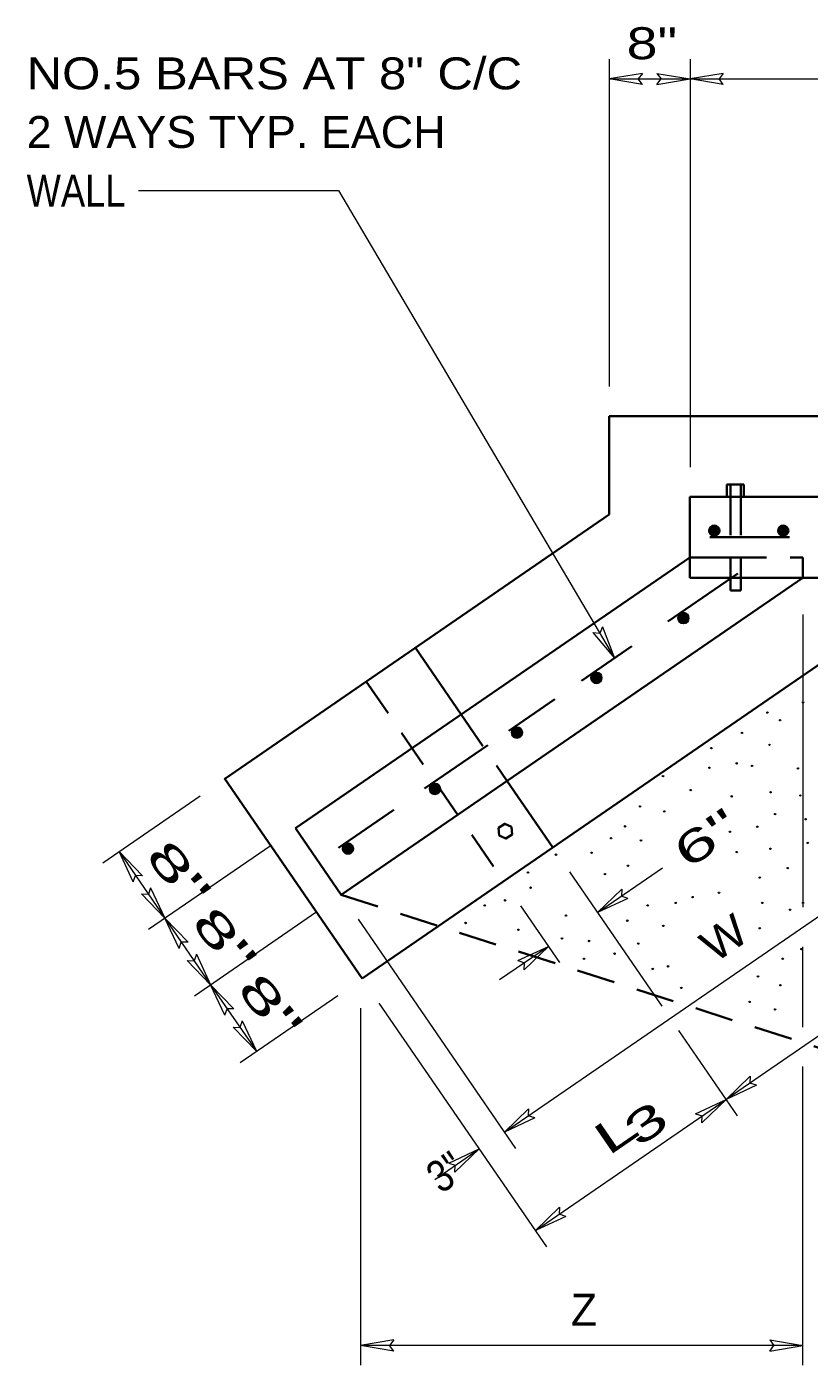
# Model space of a CAD drawing. Extents: x 178962.5 to 178977.5, y 178951.2 to 178972.9.
# Drawn here: x 178970.1 to 178973.41, y 178967.18 to 178972.83 of the extents above; entities that cross this region are included whole.
import ezdxf
from ezdxf.enums import TextEntityAlignment as Align

# ---------------------------------------------------------------- set-up
doc = ezdxf.new("R2010")
doc.units = 0
doc.header["$LTSCALE"] = 0.054
doc.linetypes.add('LONG_DASHED', pattern=[7.5, 6, -1.5])
doc.linetypes.add('MEDIUM_DASHED', pattern=[4.5, 3, -1.5])
for name, color, linetype, lineweight in [('1', 7, 'Continuous', 35), ('10', 7, 'Continuous', 13), ('12', 7, 'Continuous', 53), ('6', 7, 'Continuous', 13)]:
    doc.layers.add(name, color=color, linetype=linetype, lineweight=lineweight)

msp = doc.modelspace()

# ---------------------------------------------------------------- linework, layer by layer
at = {"layer": '1'}
for p, q in [((178972.56175, 178970.77058), (178972.56175, 178971.18683)), ((178972.56175, 178971.18683), (178973.67117, 178971.18683)), ((178973.13008, 178970.89825), (178973.05833, 178970.89825)), ((178973.05833, 178970.89825), (178973.05833, 178970.8455)), ((178973.07325, 178970.897), (178973.07325, 178970.8455)), ((178973.11708, 178970.89742), (178973.11708, 178970.8455)), ((178973.13008, 178970.89825), (178973.13008, 178970.8455)), ((178972.9015, 178970.8455), (178972.9015, 178970.50417)), ((178975.7175, 178970.8455), (178972.9015, 178970.8455)), ((178973.01008, 178970.72417), (178972.98367, 178970.7005)), ((178973.00217, 178970.72442), (178972.98417, 178970.70842)), ((178973.01583, 178970.72192), (178972.98517, 178970.6945)), ((178973.02033, 178970.71867), (178972.98792, 178970.68967)), ((178973.02383, 178970.71442), (178972.99167, 178970.68575)), ((178973.02617, 178970.70925), (178972.99658, 178970.68283)), ((178973.02717, 178970.70283), (178973.00283, 178970.68117)), ((178973.02525, 178970.69375), (178973.01217, 178970.682)), ((178973.301, 178970.72417), (178973.2745, 178970.7005)), ((178973.29308, 178970.72442), (178973.27517, 178970.70842)), ((178973.30675, 178970.72192), (178973.276, 178970.69458)), ((178973.31117, 178970.71875), (178973.27883, 178970.68975)), ((178973.31475, 178970.71442), (178973.28258, 178970.68575)), ((178973.31717, 178970.70933), (178973.2875, 178970.68275)), ((178973.31808, 178970.70283), (178973.29383, 178970.68108)), ((178973.31617, 178970.69375), (178973.30308, 178970.68208)), ((178972.98683, 178970.67483), (178973.32233, 178970.67483)), ((178972.9015, 178970.58992), (178971.23658, 178969.4455)), ((178973.10483, 178970.52225), (178972.80867, 178970.31892)), ((178973.37925, 178970.50417), (178971.42992, 178969.16417)), ((178975.7175, 178970.50417), (178972.9015, 178970.50417)), ((178972.87992, 178970.35492), (178972.85342, 178970.33125)), ((178972.872, 178970.35517), (178972.85408, 178970.33917)), ((178972.88567, 178970.35275), (178972.85492, 178970.32533)), ((178972.89008, 178970.3495), (178972.85775, 178970.3205)), ((178972.89367, 178970.34525), (178972.86158, 178970.31658)), ((178972.89608, 178970.34008), (178972.86642, 178970.31358)), ((178972.89708, 178970.33358), (178972.87275, 178970.31192)), ((178972.89508, 178970.32458), (178972.882, 178970.31283)), ((178971.74325, 178970.208), (178971.93658, 178969.92667)), ((178972.44492, 178970.069), (178972.65658, 178970.21442)), ((178973.48525, 178970.16283), (178971.51783, 178968.81042)), ((178972.51208, 178970.10208), (178972.48567, 178970.07842)), ((178972.50425, 178970.10233), (178972.48625, 178970.08633)), ((178972.51792, 178970.09983), (178972.48717, 178970.07242)), ((178972.52233, 178970.09658), (178972.49, 178970.06758)), ((178972.52592, 178970.09233), (178972.49367, 178970.06375)), ((178972.52825, 178970.08717), (178972.49867, 178970.06075)), ((178972.52925, 178970.08075), (178972.50492, 178970.059)), ((178972.52733, 178970.07175), (178972.51417, 178970.05992)), ((178972.13783, 178969.85792), (178972.33217, 178969.9915)), ((178972.17658, 178969.87142), (178972.15017, 178969.84775)), ((178972.16875, 178969.87175), (178972.15075, 178969.85575)), ((178972.18233, 178969.86933), (178972.15167, 178969.84183)), ((178972.18692, 178969.86608), (178972.15442, 178969.83708)), ((178972.19033, 178969.86175), (178972.15825, 178969.83308)), ((178972.19275, 178969.85667), (178972.16317, 178969.83008)), ((178972.19375, 178969.85008), (178972.16942, 178969.82842)), ((178972.19183, 178969.84108), (178972.17858, 178969.82933)), ((178972.04925, 178969.79708), (178971.78142, 178969.613)), ((178971.83033, 178969.63333), (178971.80383, 178969.60967)), ((178971.82242, 178969.6335), (178971.80442, 178969.6175)), ((178971.83608, 178969.63117), (178971.80533, 178969.60375)), ((178971.8405, 178969.62792), (178971.80808, 178969.59883)), ((178971.84408, 178969.62367), (178971.81192, 178969.59492)), ((178971.84642, 178969.6185), (178971.81675, 178969.59192)), ((178971.84742, 178969.612), (178971.82308, 178969.59033)), ((178972.13, 178969.64533), (178972.32333, 178969.36417)), ((178971.8455, 178969.60292), (178971.83242, 178969.59117)), ((178971.41775, 178969.36292), (178971.65133, 178969.52358)), ((178971.23658, 178969.4455), (178971.42992, 178969.16417)), ((178971.463, 178969.38092), (178971.43658, 178969.35725)), ((178971.45517, 178969.38117), (178971.43717, 178969.36517)), ((178971.46883, 178969.37875), (178971.43808, 178969.35133)), ((178971.47325, 178969.3755), (178971.44083, 178969.3465)), ((178971.47683, 178969.37125), (178971.44458, 178969.3425)), ((178971.47917, 178969.36608), (178971.4495, 178969.33958)), ((178971.48017, 178969.35958), (178971.45583, 178969.33792)), ((178971.47817, 178969.35058), (178971.46508, 178969.33875))]:
    msp.add_line(p, q, dxfattribs=at)
at = {"layer": '1', "linetype": 'MEDIUM_DASHED'}
for p, q in [((178973.11708, 178970.8455), (178973.11708, 178970.4505)), ((178971.5355, 178970.06517), (178972.11558, 178969.22133)), ((178971.93667, 178969.92667), (178972.13008, 178969.64533)), ((178971.42992, 178969.16417), (178975.37617, 178967.9015))]:
    msp.add_line(p, q, dxfattribs=at)
msp.add_lwpolyline([(178973.07325, 178970.8455), (178973.07325, 178970.4505), (178973.11708, 178970.4505)], dxfattribs=at)
at = {"layer": '1'}
msp.add_lwpolyline([(178972.56175, 178970.77058), (178970.93775, 178969.65425), (178971.51783, 178968.81042)], dxfattribs=at)
at = {"layer": '1', "linetype": 'LONG_DASHED'}
msp.add_lwpolyline([(178972.9015, 178970.5895), (178973.37942, 178970.5895), (178973.37942, 178970.50417)], dxfattribs=at)
at = {"layer": '1'}
msp.add_lwpolyline([(178972.14858, 178969.45108), (178972.151, 178969.41992), (178972.12525, 178969.40225), (178972.097, 178969.41567), (178972.09458, 178969.44683), (178972.12033, 178969.4645)], close=True, dxfattribs=at)
for centre in [(178973.00533, 178970.70282), (178973.29627, 178970.70281), (178972.87521, 178970.33356), (178972.50739, 178970.08072), (178972.1719, 178969.8501), (178971.82554, 178969.61201), (178971.45828, 178969.35955)]:
    msp.add_circle(centre, 0.02184, dxfattribs=at)
at = {"layer": '10'}
for p, q in [((178972.56175, 178972.69442), (178972.56175, 178971.31183)), ((178972.90308, 178972.69442), (178972.90308, 178970.9705)), ((178972.70175, 178972.63442), (178972.56175, 178972.61108)), ((178972.70175, 178972.58775), (178972.56175, 178972.61108)), ((178972.70175, 178972.63442), (178972.68425, 178972.61108)), ((178972.70175, 178972.58775), (178972.68425, 178972.61108)), ((178972.76308, 178972.63442), (178972.90308, 178972.61108)), ((178972.76308, 178972.63442), (178972.78058, 178972.61108)), ((178972.76308, 178972.63442), (178972.90308, 178972.61108)), ((178972.76308, 178972.63442), (178972.78058, 178972.61108)), ((178972.76308, 178972.58775), (178972.90308, 178972.61108)), ((178972.76308, 178972.58775), (178972.78058, 178972.61108)), ((178972.76308, 178972.58775), (178972.90308, 178972.61108)), ((178972.76308, 178972.58775), (178972.78058, 178972.61108)), ((178973.04308, 178972.63442), (178972.90308, 178972.61108)), ((178973.04308, 178972.63442), (178972.90308, 178972.61108)), ((178973.04308, 178972.58775), (178972.90308, 178972.61108)), ((178973.04308, 178972.58775), (178972.90308, 178972.61108)), ((178973.04308, 178972.63442), (178973.02558, 178972.61108)), ((178973.04308, 178972.63442), (178973.02558, 178972.61108)), ((178973.04308, 178972.58775), (178973.02558, 178972.61108)), ((178973.04308, 178972.58775), (178973.02558, 178972.61108)), ((178970.57308, 178972.13958), (178971.41783, 178972.13958)), ((178971.41783, 178972.13958), (178972.58367, 178970.16433)), ((178973.37942, 178970.348), (178973.37942, 178969.11175)), ((178972.53258, 178970.29675), (178972.52142, 178970.26983)), ((178972.53258, 178970.29675), (178972.58367, 178970.16433)), ((178972.49242, 178970.273), (178972.58367, 178970.16433)), ((178972.49242, 178970.273), (178972.52142, 178970.26983)), ((178970.4225, 178969.30008), (178970.8345, 178969.58333)), ((178972.11883, 178968.16183), (178974.06817, 178969.50183)), ((178970.55125, 178969.21875), (178970.49117, 178969.34733)), ((178970.58975, 178969.24525), (178970.49117, 178969.34733)), ((178970.61592, 178969.01883), (178971.13358, 178969.37475)), ((178972.51217, 178969.0895), (178972.78683, 178969.27833)), ((178970.55125, 178969.21875), (178970.56058, 178969.24642)), ((178970.58975, 178969.24525), (178970.56058, 178969.24642)), ((178972.39417, 178969.26117), (178972.78375, 178968.69467)), ((178970.586, 178969.16817), (178970.68458, 178969.066)), ((178970.586, 178969.16817), (178970.61517, 178969.167)), ((178970.62458, 178969.19467), (178970.61517, 178969.167)), ((178970.62458, 178969.19467), (178970.68458, 178969.066)), ((178972.61433, 178969.188), (178972.51217, 178969.0895)), ((178972.61433, 178969.188), (178972.61317, 178969.15892)), ((178972.64075, 178969.14958), (178972.61317, 178969.15892)), ((178974.30425, 178969.15858), (178973.05517, 178968.29992)), ((178972.18642, 178969.11833), (178972.35167, 178968.878)), ((178972.64075, 178969.14958), (178972.51217, 178969.0895)), ((178970.74467, 178968.93733), (178970.68458, 178969.066)), ((178970.78325, 178968.96392), (178970.68458, 178969.066)), ((178970.80933, 178968.7375), (178971.327, 178969.09342)), ((178971.50075, 178969.06117), (178972.16608, 178968.09325)), ((178970.74467, 178968.93733), (178970.754, 178968.965)), ((178970.78325, 178968.96392), (178970.754, 178968.965)), ((178972.30442, 178968.94667), (178972.09842, 178968.80508)), ((178972.17583, 178968.88658), (178972.30442, 178968.94667)), ((178972.20233, 178968.84808), (178972.30442, 178968.94667)), ((178973.37942, 178968.60617), (178973.37942, 178968.94508)), ((178970.77933, 178968.88692), (178970.878, 178968.78467)), ((178970.77933, 178968.88692), (178970.8085, 178968.88567)), ((178970.818, 178968.91342), (178970.8085, 178968.88567)), ((178970.818, 178968.91342), (178970.878, 178968.78467)), ((178972.17583, 178968.88658), (178972.2035, 178968.87725)), ((178972.20233, 178968.84808), (178972.2035, 178968.87725)), ((178970.93817, 178968.65592), (178970.878, 178968.78467)), ((178970.97675, 178968.6825), (178970.878, 178968.78467)), ((178971.00267, 178968.45633), (178971.41475, 178968.73958)), ((178971.58867, 178968.70742), (178972.29675, 178967.67742)), ((178970.93817, 178968.65592), (178970.94742, 178968.68358)), ((178970.97675, 178968.6825), (178970.94742, 178968.68358)), ((178971.51117, 178968.68542), (178971.51117, 178967.17742)), ((178970.97258, 178968.60583), (178971.07125, 178968.5035)), ((178970.97258, 178968.60583), (178971.00175, 178968.6045)), ((178971.01125, 178968.63233), (178971.00175, 178968.6045)), ((178971.01125, 178968.63233), (178971.07125, 178968.5035)), ((178972.8545, 178968.59167), (178973.10225, 178968.23133)), ((178973.37942, 178967.17742), (178973.37942, 178968.4395)), ((178973.15733, 178968.39842), (178973.05517, 178968.29992)), ((178973.15733, 178968.39842), (178973.15608, 178968.36933)), ((178973.18375, 178968.36), (178973.15608, 178968.36933)), ((178973.18375, 178968.36), (178973.05517, 178968.29992)), ((178972.221, 178968.26033), (178972.11883, 178968.16183)), ((178972.221, 178968.26033), (178972.21975, 178968.23125)), ((178972.2495, 178967.74608), (178973.05517, 178968.29992)), ((178972.92658, 178968.23983), (178973.05517, 178968.29992)), ((178972.953, 178968.20142), (178973.05517, 178968.29992)), ((178972.24742, 178968.22192), (178972.11883, 178968.16183)), ((178972.24742, 178968.22192), (178972.21975, 178968.23125)), ((178972.92658, 178968.23983), (178972.95425, 178968.2305)), ((178972.953, 178968.20142), (178972.95425, 178968.2305)), ((178971.82458, 178967.9625), (178972.01208, 178968.09142)), ((178971.8835, 178968.03133), (178972.01208, 178968.09142)), ((178971.90992, 178967.99283), (178972.01208, 178968.09142)), ((178971.8835, 178968.03133), (178971.91117, 178968.022)), ((178971.90992, 178967.99283), (178971.91117, 178968.022)), ((178972.35167, 178967.84458), (178972.2495, 178967.74608)), ((178972.37808, 178967.80617), (178972.2495, 178967.74608)), ((178972.35167, 178967.84458), (178972.35042, 178967.8155)), ((178972.37808, 178967.80617), (178972.35042, 178967.8155)), ((178971.65117, 178967.28408), (178971.51117, 178967.26075)), ((178973.37942, 178967.26075), (178971.51117, 178967.26075)), ((178971.65117, 178967.23742), (178971.51117, 178967.26075)), ((178971.65117, 178967.28408), (178971.63367, 178967.26075)), ((178971.65117, 178967.23742), (178971.63367, 178967.26075)), ((178973.23942, 178967.28408), (178973.37942, 178967.26075)), ((178973.23942, 178967.28408), (178973.25692, 178967.26075)), ((178973.23942, 178967.23742), (178973.37942, 178967.26075)), ((178973.23942, 178967.23742), (178973.25692, 178967.26075))]:
    msp.add_line(p, q, dxfattribs=at)
for points in [[(178972.56175, 178972.61108), (178972.90308, 178972.61108), (178975.7175, 178972.61108)], [(178970.49117, 178969.34733), (178970.6845, 178969.066), (178970.87792, 178968.78467), (178971.07125, 178968.5035)]]:
    msp.add_lwpolyline(points, dxfattribs=at)
at = {"layer": '6'}
for centre in [(178973.38029, 178969.97713), (178973.22963, 178969.93429), (178973.28346, 178969.90212), (178973.12204, 178969.84854), (178972.99296, 178969.78421), (178973.23853, 178969.79811), (178972.78862, 178969.66629), (178972.98503, 178969.70111), (178973.10054, 178969.71996), (178973.16512, 178969.70921), (178973.35871, 178969.69846), (178972.90607, 178969.60697), (178973.07904, 178969.58054), (178973.24276, 178969.59817), (178973.36911, 178969.58411), (178972.69179, 178969.53771), (178972.79417, 178969.51689), (178973.26196, 178969.50554), (178972.62869, 178969.45373), (178973.18663, 178969.45196), (178973.39104, 178969.48412), (178972.56973, 178969.40386), (178972.69563, 178969.39445), (178973.071, 178969.43065), (178973.4001, 178969.38372), (178972.33679, 178969.33404), (178972.48701, 178969.34244), (178973.10054, 178969.34479), (178973.24236, 178969.35894), (178972.64028, 178969.28736), (178973.31563, 178969.27743), (178972.21837, 178969.25904), (178972.54335, 178969.25184), (178973.19737, 178969.23762), (178972.22921, 178969.19471), (178972.91353, 178969.15486), (178973.02521, 178969.17329), (178972.03554, 178969.11971), (178972.12162, 178969.14112), (178972.72404, 178969.11971), (178972.84238, 178969.13038), (178973.20813, 178969.13038), (178973.32561, 178969.10136), (178973.38029, 178969.13038), (178971.95491, 178969.04562), (178972.37874, 178969.07712), (178972.63796, 178969.05537), (178972.17804, 178969.01713), (178972.79024, 178969.03324), (178973.19737, 178969.02321), (178972.362, 178968.9803), (178972.47662, 178968.96962), (178972.68419, 178968.95861), (178973.37353, 178968.93544), (178972.45513, 178968.89462), (178972.58421, 178968.91604), (178973.29421, 178968.89462), (178972.74554, 178968.85171), (178972.81012, 178968.86246), (178973.19009, 178968.81983), (178972.86619, 178968.77146), (178973.2849, 178968.78276), (178973.15437, 178968.71238), (178973.26196, 178968.68021)]:
    msp.add_circle(centre, 0.00298, dxfattribs=at)

# ---------------------------------------------------------------- texts
at = {"layer": '12', "width": 1.3}
msp.add_text('8"', height=0.135, dxfattribs=at).set_placement((178972.74188, 178972.69442), align=Align.CENTER)
at = {"layer": '12'}
for s, width, p in [('NO.5 BARS AT 8" C/C', 1.15, (178970.10083, 178972.56708)), ('2 WAYS TYP. EACH', 1.05, (178970.10083, 178972.31958)), ('WALL', 0.85, (178970.10083, 178972.07208))]:
    msp.add_text(s, height=0.135, dxfattribs=dict(at, width=width)).set_placement(p)
at = {"layer": '12', "width": 1.7}
msp.add_text('6"', height=0.135, rotation=34.496, dxfattribs=at).set_placement((178972.89367, 178969.26992))
at = {"layer": '12'}
for s, rotation, width, p in [('8"', 309.165, 1.8, (178970.69121, 178969.21117)), ('8"', 309.164, 1.8, (178970.88463, 178968.92984)), ('W', 34.506, 1.1, (178973.08455, 178968.92674)), ('8"', 309.169, 1.8, (178971.07797, 178968.64859)), ('3', 34.508, 1.7, (178972.75409, 178968.14338)), ('L', 34.504, 1.7, (178972.62747, 178968.10693))]:
    msp.add_text(s, height=0.135, rotation=rotation, dxfattribs=dict(at, width=width)).set_placement(p, align=Align.CENTER)
at = {"layer": '12', "width": 0.85}
msp.add_text('3"', height=0.135, rotation=34.507, dxfattribs=at).set_placement((178971.96627, 178967.97794), align=Align.RIGHT)
at = {"layer": '12'}
msp.add_text('Z', height=0.135, dxfattribs=at).set_placement((178972.45475, 178967.34408), align=Align.CENTER)

doc.saveas('drawing.dxf')
